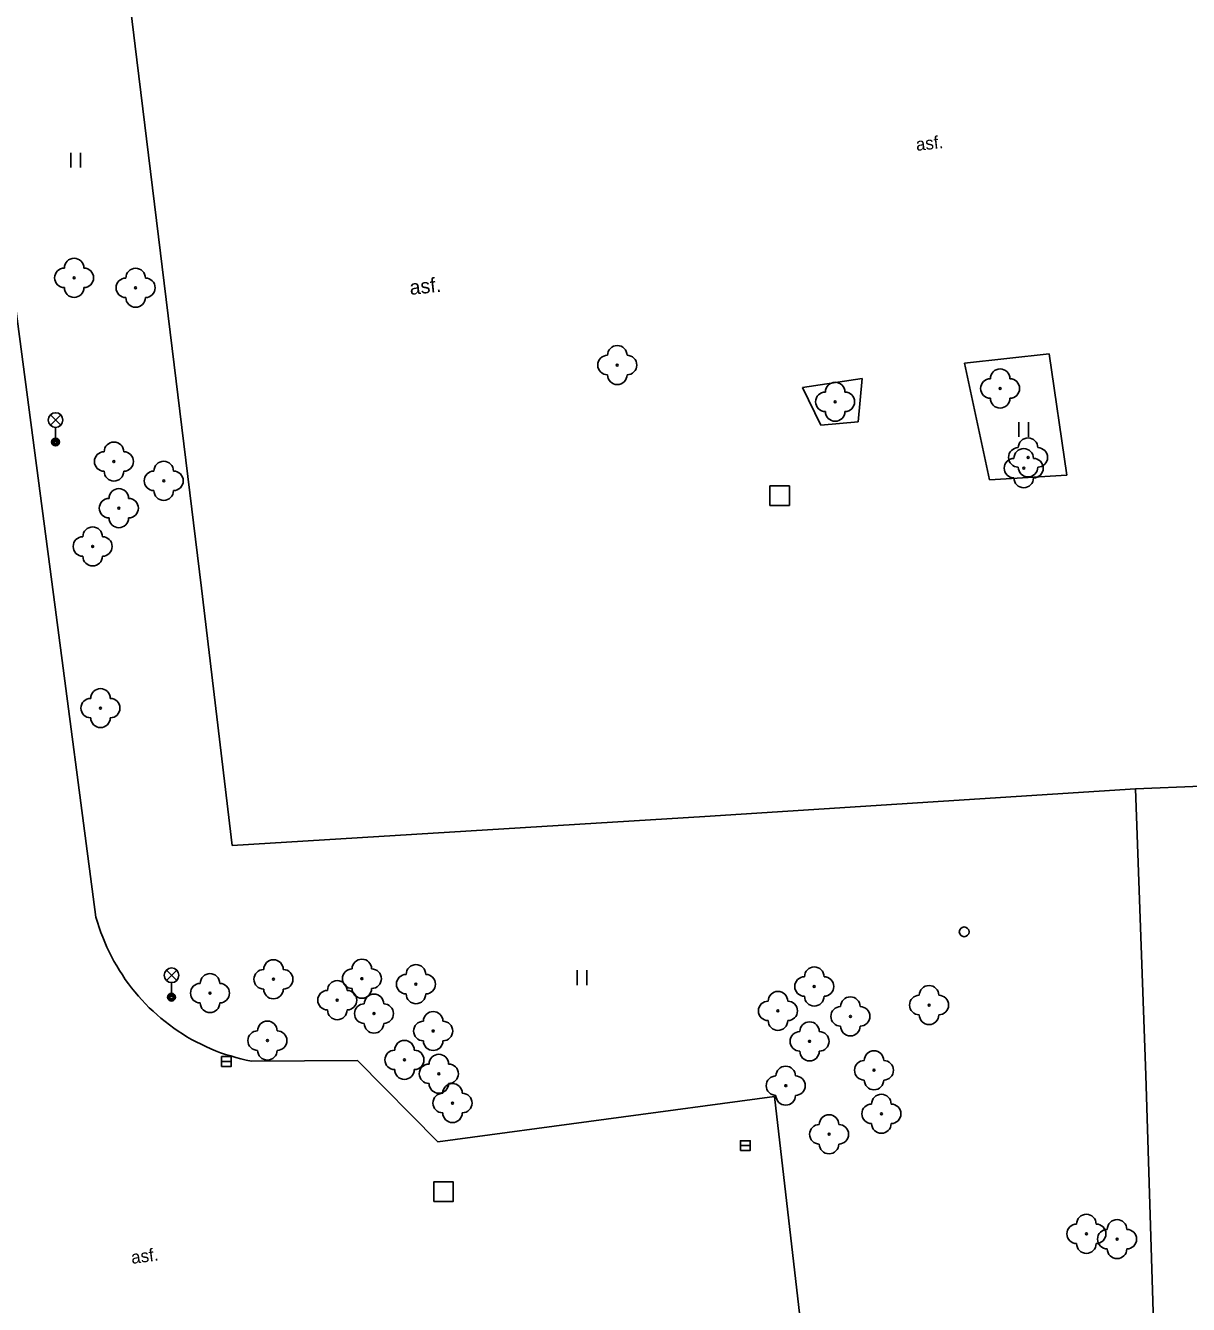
# Model space of a CAD drawing. Extents: x -641829 to -641525, y -1114855 to -1114359.
# Drawn here: x -641712.4 to -641652.8, y -1114601.3 to -1114535.8 of the extents above; entities that cross this region are included whole.
import ezdxf

# ---------------------------------------------------------------- set-up
doc = ezdxf.new("R2010")
doc.units = 0
for name, color, linetype in [('Vrstva 10', 7, 'Continuous'), ('Vrstva 11', 7, 'Continuous'), ('Vrstva 22', 7, 'Continuous'), ('Vrstva 26', 7, 'Continuous'), ('Vrstva 27', 7, 'Continuous'), ('Vrstva 28', 7, 'Continuous'), ('Vrstva 33', 7, 'Continuous'), ('Vrstva 36', 7, 'Continuous'), ('Vrstva 40', 7, 'Continuous'), ('Vrstva 41', 7, 'Continuous')]:
    doc.layers.add(name, color=color, linetype=linetype)

msp = doc.modelspace()

# ---------------------------------------------------------------- linework, layer by layer
at = {"layer": 'Vrstva 10'}
for p, q in [((-641710.09, -1114510.39), (-641706.68, -1114537.6)), ((-641710.95, -1114564.98), (-641715.11, -1114533.57)), ((-641706.68, -1114537.6), (-641703.37, -1114564.66)), ((-641659.96, -1114552.66), (-641664.3, -1114553.13)), ((-641664.3, -1114553.13), (-641663.02, -1114559.1)), ((-641659.05, -1114558.87), (-641659.96, -1114552.66)), ((-641669.54, -1114553.92), (-641672.59, -1114554.37)), ((-641672.59, -1114554.37), (-641671.66, -1114556.3)), ((-641669.74, -1114556.13), (-641669.54, -1114553.92)), ((-641669.74, -1114556.13), (-641671.66, -1114556.3)), ((-641663.02, -1114559.1), (-641659.05, -1114558.87)), ((-641708.78, -1114581.51), (-641710.95, -1114564.98)), ((-641703.37, -1114564.66), (-641701.81, -1114577.83)), ((-641655.53, -1114574.94), (-641652.17, -1114574.8)), ((-641677.6, -1114576.36), (-641655.53, -1114574.94)), ((-641701.81, -1114577.83), (-641677.6, -1114576.36)), ((-641708.78, -1114581.51), (-641708.7, -1114581.77)), ((-641708.7, -1114581.77), (-641708.62, -1114582.03)), ((-641708.62, -1114582.03), (-641708.53, -1114582.29)), ((-641708.53, -1114582.29), (-641708.43, -1114582.54)), ((-641708.43, -1114582.54), (-641708.33, -1114582.79)), ((-641708.33, -1114582.79), (-641708.22, -1114583.04)), ((-641708.22, -1114583.04), (-641708.11, -1114583.29)), ((-641708.11, -1114583.29), (-641707.99, -1114583.53)), ((-641707.99, -1114583.53), (-641707.86, -1114583.77)), ((-641707.86, -1114583.77), (-641707.72, -1114584.01)), ((-641707.72, -1114584.01), (-641707.58, -1114584.24)), ((-641707.58, -1114584.24), (-641707.43, -1114584.47)), ((-641707.43, -1114584.47), (-641707.28, -1114584.7)), ((-641707.28, -1114584.7), (-641707.12, -1114584.92)), ((-641707.12, -1114584.92), (-641706.96, -1114585.13)), ((-641706.96, -1114585.13), (-641706.79, -1114585.34)), ((-641706.79, -1114585.34), (-641706.61, -1114585.55)), ((-641706.61, -1114585.55), (-641706.43, -1114585.75)), ((-641706.43, -1114585.75), (-641706.24, -1114585.95)), ((-641706.24, -1114585.95), (-641706.05, -1114586.15)), ((-641706.05, -1114586.15), (-641705.85, -1114586.33)), ((-641705.85, -1114586.33), (-641705.65, -1114586.51)), ((-641705.65, -1114586.51), (-641705.45, -1114586.69)), ((-641705.45, -1114586.69), (-641705.24, -1114586.86)), ((-641705.24, -1114586.86), (-641705.02, -1114587.03)), ((-641705.02, -1114587.03), (-641704.8, -1114587.19)), ((-641704.8, -1114587.19), (-641704.57, -1114587.34)), ((-641704.57, -1114587.34), (-641704.35, -1114587.49)), ((-641704.35, -1114587.49), (-641704.12, -1114587.63)), ((-641704.12, -1114587.63), (-641703.88, -1114587.77)), ((-641703.88, -1114587.77), (-641703.64, -1114587.9)), ((-641703.64, -1114587.9), (-641703.4, -1114588.02)), ((-641703.4, -1114588.02), (-641703.15, -1114588.14)), ((-641703.15, -1114588.14), (-641702.9, -1114588.25)), ((-641702.9, -1114588.25), (-641702.65, -1114588.35)), ((-641702.65, -1114588.35), (-641702.4, -1114588.45)), ((-641702.4, -1114588.45), (-641702.14, -1114588.54)), ((-641702.14, -1114588.54), (-641701.88, -1114588.62)), ((-641701.88, -1114588.62), (-641701.62, -1114588.7)), ((-641701.62, -1114588.7), (-641701.36, -1114588.77)), ((-641701.36, -1114588.77), (-641701.09, -1114588.83)), ((-641701.09, -1114588.83), (-641700.82, -1114588.89)), ((-641695.39, -1114588.85), (-641700.82, -1114588.89)), ((-641691.27, -1114593.01), (-641695.39, -1114588.85)), ((-641674.03, -1114590.7), (-641691.27, -1114593.01)), ((-641671.74, -1114610.42), (-641674.03, -1114590.7))]:
    msp.add_line(p, q, dxfattribs=at)
at = {"layer": 'Vrstva 11'}
for p, q in [((-641655.01, -1114589.6), (-641655.53, -1114574.94)), ((-641654.56, -1114604.27), (-641655.01, -1114589.6))]:
    msp.add_line(p, q, dxfattribs=at)
at = {"layer": 'Vrstva 22'}
for centre in [(-641709.9, -1114548.76), (-641706.75, -1114549.27), (-641682.08, -1114553.23), (-641662.47, -1114554.43), (-641670.92, -1114555.11), (-641707.86, -1114558.17), (-641661.04, -1114557.96), (-641661.26, -1114558.51), (-641705.31, -1114559.16), (-641707.61, -1114560.56), (-641708.95, -1114562.52), (-641708.55, -1114570.8), (-641695.16, -1114584.66), (-641699.69, -1114584.69), (-641692.39, -1114584.94), (-641671.99, -1114585.06), (-641702.94, -1114585.4), (-641696.42, -1114585.76), (-641694.54, -1114586.45), (-641673.85, -1114586.31), (-641670.14, -1114586.59), (-641666.11, -1114586.01), (-641700, -1114587.83), (-641691.51, -1114587.34), (-641672.23, -1114587.87), (-641692.98, -1114588.82), (-641691.22, -1114589.53), (-641668.93, -1114589.35), (-641673.45, -1114590.14), (-641690.52, -1114591.03), (-641668.55, -1114591.58), (-641671.23, -1114592.63), (-641658.05, -1114597.73), (-641656.48, -1114598)]:
    msp.add_circle(centre, 0.05, dxfattribs=at)
for centre, start, end in [((-641709.9, -1114548.26), 0, 180), ((-641710.4, -1114548.76), 90, 270), ((-641709.4, -1114548.76), 270, 90), ((-641706.75, -1114548.77), 0, 180), ((-641709.9, -1114549.26), 180, 0), ((-641707.25, -1114549.27), 90, 270), ((-641706.25, -1114549.27), 270, 90), ((-641706.75, -1114549.77), 180, 0), ((-641682.08, -1114552.73), 0, 180), ((-641682.58, -1114553.23), 90, 270), ((-641681.58, -1114553.23), 270, 90), ((-641682.08, -1114553.73), 180, 0), ((-641662.47, -1114553.93), 0, 180), ((-641670.92, -1114554.61), 0, 180), ((-641662.97, -1114554.43), 90, 270), ((-641661.97, -1114554.43), 270, 90), ((-641671.42, -1114555.11), 90, 270), ((-641670.42, -1114555.11), 270, 90), ((-641662.47, -1114554.93), 180, 0), ((-641670.92, -1114555.61), 180, 0), ((-641661.04, -1114557.46), 0, 180), ((-641708.36, -1114558.17), 90, 270), ((-641707.86, -1114557.67), 0, 180), ((-641707.36, -1114558.17), 270, 90), ((-641661.54, -1114557.96), 90, 270), ((-641661.26, -1114558.01), 0, 180), ((-641660.54, -1114557.96), 270, 90), ((-641705.31, -1114558.66), 0, 180), ((-641661.76, -1114558.51), 90, 270), ((-641660.76, -1114558.51), 270, 90), ((-641707.86, -1114558.67), 180, 0), ((-641705.81, -1114559.16), 90, 270), ((-641704.81, -1114559.16), 270, 90), ((-641661.26, -1114559.01), 180, 0), ((-641661.04, -1114558.46), 180, 0), ((-641707.61, -1114560.06), 0, 180), ((-641705.31, -1114559.66), 180, 0), ((-641708.11, -1114560.56), 90, 270), ((-641707.11, -1114560.56), 270, 90), ((-641708.95, -1114562.02), 0, 180), ((-641707.61, -1114561.06), 180, 0), ((-641709.45, -1114562.52), 90, 270), ((-641708.45, -1114562.52), 270, 90), ((-641708.95, -1114563.02), 180, 0), ((-641708.55, -1114570.3), 0, 180), ((-641709.05, -1114570.8), 90, 270), ((-641708.05, -1114570.8), 270, 90), ((-641708.55, -1114571.3), 180, 0), ((-641699.69, -1114584.19), 0, 180), ((-641695.16, -1114584.16), 0, 180), ((-641692.39, -1114584.44), 0, 180), ((-641702.94, -1114584.9), 0, 180), ((-641700.19, -1114584.69), 90, 270), ((-641699.19, -1114584.69), 270, 90), ((-641695.66, -1114584.66), 90, 270), ((-641694.66, -1114584.66), 270, 90), ((-641692.89, -1114584.94), 90, 270), ((-641691.89, -1114584.94), 270, 90), ((-641672.49, -1114585.06), 90, 270), ((-641671.99, -1114584.56), 0, 180), ((-641671.49, -1114585.06), 270, 90), ((-641703.44, -1114585.4), 90, 270), ((-641702.44, -1114585.4), 270, 90), ((-641699.69, -1114585.19), 180, 0), ((-641696.92, -1114585.76), 90, 270), ((-641696.42, -1114585.26), 0, 180), ((-641695.92, -1114585.76), 270, 90), ((-641695.16, -1114585.16), 180, 0), ((-641666.11, -1114585.51), 0, 180), ((-641702.94, -1114585.9), 180, 0), ((-641694.54, -1114585.95), 0, 180), ((-641692.39, -1114585.44), 180, 0), ((-641674.35, -1114586.31), 90, 270), ((-641673.85, -1114585.81), 0, 180), ((-641673.35, -1114586.31), 270, 90), ((-641671.99, -1114585.56), 180, 0), ((-641670.14, -1114586.09), 0, 180), ((-641666.61, -1114586.01), 90, 270), ((-641665.61, -1114586.01), 270, 90), ((-641696.42, -1114586.26), 180, 0), ((-641695.04, -1114586.45), 90, 270), ((-641694.04, -1114586.45), 270, 90), ((-641691.51, -1114586.84), 0, 180), ((-641670.64, -1114586.59), 90, 270), ((-641669.64, -1114586.59), 270, 90), ((-641666.11, -1114586.51), 180, 0), ((-641700, -1114587.33), 0, 180), ((-641694.54, -1114586.95), 180, 0), ((-641692.01, -1114587.34), 90, 270), ((-641691.01, -1114587.34), 270, 90), ((-641673.85, -1114586.81), 180, 0), ((-641672.23, -1114587.37), 0, 180), ((-641670.14, -1114587.09), 180, 0), ((-641700.5, -1114587.83), 90, 270), ((-641699.5, -1114587.83), 270, 90), ((-641692.98, -1114588.32), 0, 180), ((-641691.51, -1114587.84), 180, 0), ((-641672.73, -1114587.87), 90, 270), ((-641671.73, -1114587.87), 270, 90), ((-641700, -1114588.33), 180, 0), ((-641693.48, -1114588.82), 90, 270), ((-641692.48, -1114588.82), 270, 90), ((-641691.22, -1114589.03), 0, 180), ((-641672.23, -1114588.37), 180, 0), ((-641668.93, -1114588.85), 0, 180), ((-641691.72, -1114589.53), 90, 270), ((-641690.72, -1114589.53), 270, 90), ((-641673.45, -1114589.64), 0, 180), ((-641669.43, -1114589.35), 90, 270), ((-641668.43, -1114589.35), 270, 90), ((-641692.98, -1114589.32), 180, 0), ((-641673.95, -1114590.14), 90, 270), ((-641672.95, -1114590.14), 270, 90), ((-641668.93, -1114589.85), 180, 0), ((-641691.22, -1114590.03), 180, 0), ((-641691.02, -1114591.03), 90, 270), ((-641690.52, -1114590.53), 0, 180), ((-641690.02, -1114591.03), 270, 90), ((-641673.45, -1114590.64), 180, 0), ((-641669.05, -1114591.58), 90, 270), ((-641668.55, -1114591.08), 0, 180), ((-641668.05, -1114591.58), 270, 90), ((-641690.52, -1114591.53), 180, 0), ((-641671.23, -1114592.13), 0, 180), ((-641671.73, -1114592.63), 90, 270), ((-641670.73, -1114592.63), 270, 90), ((-641668.55, -1114592.08), 180, 0), ((-641671.23, -1114593.13), 180, 0), ((-641658.05, -1114597.23), 0, 180), ((-641656.48, -1114597.5), 0, 180), ((-641658.55, -1114597.73), 90, 270), ((-641657.55, -1114597.73), 270, 90), ((-641656.98, -1114598), 90, 270), ((-641655.98, -1114598), 270, 90), ((-641658.05, -1114598.23), 180, 0), ((-641656.48, -1114598.5), 180, 0)]:
    msp.add_arc(centre, 0.5, start, end, dxfattribs=at)
at = {"layer": 'Vrstva 26'}
for points in [[(-641674.26, -1114560.42), (-641673.26, -1114560.42), (-641673.26, -1114559.42), (-641674.26, -1114559.42)], [(-641691.48, -1114596.07), (-641690.48, -1114596.07), (-641690.48, -1114595.07), (-641691.48, -1114595.07)]]:
    msp.add_lwpolyline(points, close=True, dxfattribs=at)
at = {"layer": 'Vrstva 27'}
for p, q in [((-641702.35, -1114588.9), (-641701.85, -1114588.9)), ((-641675.77, -1114593.21), (-641675.27, -1114593.21))]:
    msp.add_line(p, q, dxfattribs=at)
for points in [[(-641702.35, -1114589.15), (-641701.85, -1114589.15), (-641701.85, -1114588.65), (-641702.35, -1114588.65)], [(-641675.77, -1114593.46), (-641675.27, -1114593.46), (-641675.27, -1114592.96), (-641675.77, -1114592.96)]]:
    msp.add_lwpolyline(points, close=True, dxfattribs=at)
at = {"layer": 'Vrstva 28'}
msp.add_circle((-641664.31, -1114582.26), 0.25, dxfattribs=at)
at = {"layer": 'Vrstva 33'}
for p, q in [((-641711.116, -1114556.31), (-641710.584, -1114555.78)), ((-641711.116, -1114555.78), (-641710.584, -1114556.31)), ((-641710.85, -1114556.42), (-641710.85, -1114557.17)), ((-641705.176, -1114584.75), (-641704.644, -1114584.22)), ((-641705.176, -1114584.22), (-641704.644, -1114584.75)), ((-641704.91, -1114584.86), (-641704.91, -1114585.61))]:
    msp.add_line(p, q, dxfattribs=at)
for centre, radius in [((-641710.85, -1114556.045), 0.375), ((-641710.85, -1114557.17), 0.2), ((-641710.85, -1114557.17), 0.145), ((-641710.85, -1114557.17), 0.0876), ((-641704.91, -1114584.485), 0.375), ((-641704.91, -1114585.61), 0.2), ((-641704.91, -1114585.61), 0.145), ((-641704.91, -1114585.61), 0.0876)]:
    msp.add_circle(centre, radius, dxfattribs=at)
at = {"layer": 'Vrstva 36'}
for p, q in [((-641710.074, -1114543.102), (-641710.074, -1114542.354)), ((-641709.574, -1114543.102), (-641709.574, -1114542.354)), ((-641661.514, -1114556.904), (-641661.514, -1114556.152)), ((-641661.014, -1114556.904), (-641661.014, -1114556.152)), ((-641684.134, -1114584.984), (-641684.134, -1114584.232)), ((-641683.634, -1114584.984), (-641683.634, -1114584.232))]:
    msp.add_line(p, q, dxfattribs=at)

# ---------------------------------------------------------------- texts
at = {"layer": 'Vrstva 40'}
for height, rotation, p in [(0.6499, 6.185, (-641666.75, -1114542.26)), (0.65, 7.33473, (-641706.94, -1114599.27))]:
    msp.add_text('asf.', height=height, rotation=rotation, dxfattribs=at).set_placement(p)
at = {"layer": 'Vrstva 41'}
msp.add_text('asf.', height=0.7499, rotation=6.185, dxfattribs=at).set_placement((-641692.68, -1114549.64))

doc.saveas('drawing.dxf')
